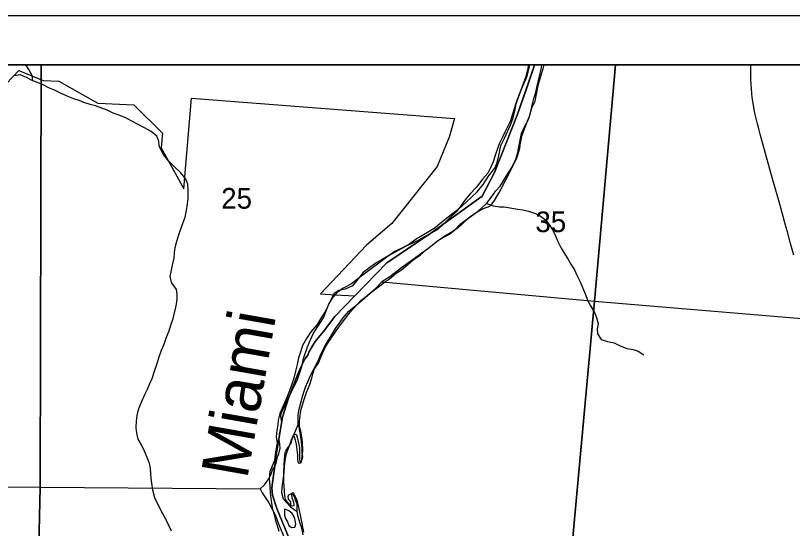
# Model space of a CAD drawing. Extents: x -38.1 to 35.9, y -2.7 to 28.5.
# Drawn here: x 10.189 to 11.759, y 18.793 to 19.831 of the extents above; entities that cross this region are included whole.
import ezdxf

# ---------------------------------------------------------------- set-up
doc = ezdxf.new("R2010")
doc.units = 0
for name, color, linetype in [('GM_X_Interchange_Ramps', 7, 'Continuous'), ('GM_X_Minor_River', 7, 'Continuous'), ('GM_X_Section', 7, 'Continuous'), ('GM_X_Township_Road', 7, 'Continuous'), ('GM_X_Township_Road_Text', 7, 'Continuous'), ('GM_X_US_Route', 7, 'Continuous'), ('SH_Border', 7, 'Continuous'), ('SH_Data', 7, 'Continuous')]:
    doc.layers.add(name, color=color, linetype=linetype)

msp = doc.modelspace()

# ---------------------------------------------------------------- linework, layer by layer
at = {"layer": 'GM_X_Interchange_Ramps'}
msp.add_lwpolyline([(11.7616, 19.346), (11.7552, 19.3694), (11.7486, 19.3933), (11.745, 19.4065), (11.7332, 19.449), (11.7292, 19.4634), (11.7188, 19.5005), (11.7044, 19.5513), (11.6938, 19.5909), (11.6918, 19.5987), (11.6885, 19.6113), (11.6838, 19.6306), (11.6825, 19.6367), (11.6793, 19.6537), (11.6777, 19.6647), (11.6769, 19.6727), (11.6767, 19.6746), (11.676, 19.682), (11.6753, 19.6926), (11.675, 19.6998), (11.6748, 19.7039), (11.6749, 19.7135), (11.6751, 19.7308)], dxfattribs=at)
at = {"layer": 'GM_X_Section'}
for points in [[(10.2234, 19.6988), (10.222, 19.7091), (10.2157, 19.7213), (10.209, 19.7308)], [(10.4494, 19.6035), (10.4366, 19.6105), (10.4234, 19.6167), (10.4114, 19.6237), (10.397, 19.6292), (10.3861, 19.6335), (10.374, 19.6393), (10.3631, 19.6436), (10.3502, 19.648), (10.3393, 19.6508), (10.3268, 19.6547), (10.317, 19.6586), (10.3064, 19.6625), (10.2928, 19.6676), (10.2792, 19.6735), (10.2683, 19.6793), (10.257, 19.684), (10.2446, 19.6906), (10.2332, 19.6949), (10.2234, 19.6988), (10.2106, 19.7051), (10.1978, 19.7109), (10.1856, 19.7084)], [(10.5039, 18.7871), (10.4976, 18.8001), (10.4932, 18.8104), (10.4862, 18.8226), (10.4765, 18.8406), (10.4699, 18.8548), (10.4659, 18.8704), (10.4635, 18.889), (10.4621, 18.902), (10.4611, 18.9145), (10.459, 18.9241), (10.4549, 18.9366), (10.449, 18.9489), (10.4431, 18.9619), (10.4364, 18.9734), (10.4336, 18.9859), (10.4322, 18.9962), (10.4327, 19.0103), (10.4344, 19.0213), (10.4376, 19.0353), (10.443, 19.0481), (10.4501, 19.0636), (10.4555, 19.075), (10.4602, 19.0863), (10.4649, 19.0965), (10.4704, 19.1132), (10.4739, 19.1249), (10.4779, 19.1382), (10.4838, 19.1537), (10.4888, 19.1654), (10.4936, 19.1798), (10.499, 19.193), (10.5022, 19.2044), (10.5069, 19.2176), (10.5113, 19.2343), (10.5137, 19.2468), (10.515, 19.257), (10.5151, 19.2665), (10.5141, 19.2764), (10.504, 19.2902), (10.5011, 19.3024), (10.5036, 19.3157), (10.5056, 19.3255), (10.5092, 19.3395), (10.5097, 19.3505), (10.5113, 19.3615), (10.5141, 19.3714), (10.5173, 19.3831), (10.5216, 19.3952), (10.5275, 19.4119), (10.5311, 19.4225), (10.5343, 19.4361), (10.5363, 19.4494), (10.5372, 19.4604), (10.5374, 19.4767), (10.5368, 19.4893), (10.5324, 19.4996), (10.5227, 19.5126), (10.5103, 19.5241), (10.4979, 19.5368), (10.4871, 19.5502), (10.479, 19.5671), (10.4779, 19.5766), (10.4743, 19.5865), (10.463, 19.5961), (10.4494, 19.6035)], [(11.1408, 19.4506), (11.1537, 19.4455), (11.1665, 19.4434), (11.1764, 19.4433), (11.2037, 19.4392), (11.2139, 19.4376), (11.2256, 19.4348), (11.2396, 19.43), (11.2497, 19.4246), (11.2606, 19.4165), (11.2685, 19.4058), (11.2752, 19.3954), (11.28, 19.3851), (11.2848, 19.3733), (11.2914, 19.3599), (11.2985, 19.3476), (11.3048, 19.3381), (11.3108, 19.3277), (11.3186, 19.3159), (11.3234, 19.3056), (11.3293, 19.293), (11.3403, 19.2662), (11.3448, 19.2551), (11.3507, 19.2433), (11.3585, 19.2299), (11.3629, 19.22), (11.3665, 19.207), (11.3645, 19.1968), (11.3648, 19.1869), (11.3726, 19.175), (11.3854, 19.1714), (11.3983, 19.1683), (11.4092, 19.1628), (11.4243, 19.1569), (11.4368, 19.1549), (11.447, 19.1517), (11.4583, 19.1444)]]:
    msp.add_lwpolyline(points, dxfattribs=at)
at = {"layer": 'GM_X_Township_Road'}
for p, q in [((10.7595, 19.0037), (10.7503, 18.9814)), ((10.7441, 18.8366), (10.7577, 18.827))]:
    msp.add_line(p, q, dxfattribs=at)
for points in [[(11.2256, 19.7308), (11.2234, 19.72), (11.2198, 19.7076), (11.2147, 19.6928), (11.2108, 19.6818), (11.2065, 19.6709), (11.2021, 19.6591), (11.1986, 19.6489), (11.1955, 19.6391), (11.1923, 19.6289), (11.1888, 19.6179), (11.1833, 19.6066), (11.1775, 19.5945), (11.1728, 19.5847), (11.1666, 19.5722), (11.1615, 19.5578), (11.1583, 19.5472), (11.154, 19.5344), (11.1489, 19.5223), (11.1435, 19.5117), (11.1331, 19.5001), (11.1196, 19.4827), (11.1073, 19.4696), (11.0969, 19.4568), (11.0873, 19.4436), (11.0792, 19.4338), (11.0673, 19.4218), (11.0535, 19.4083), (11.0427, 19.3986), (11.0298, 19.3911), (11.0168, 19.3833), (11.0049, 19.377), (10.9939, 19.3714), (10.9805, 19.3655), (10.9694, 19.3595), (10.9546, 19.3513), (10.9427, 19.3446), (10.9294, 19.3372), (10.9187, 19.3309), (10.9045, 19.3212), (10.8911, 19.3107), (10.8784, 19.2949), (10.8699, 19.2836), (10.8547, 19.2769), (10.8421, 19.2744), (10.8326, 19.2684), (10.8271, 19.2579), (10.8217, 19.2469), (10.8139, 19.2303), (10.805, 19.2171), (10.7984, 19.2054), (10.7853, 19.1904), (10.7765, 19.1772), (10.7687, 19.1632), (10.7651, 19.1515), (10.7608, 19.1382), (10.7576, 19.1249), (10.7544, 19.1109), (10.7508, 19.0969), (10.7465, 19.0825), (10.7422, 19.0715), (10.7367, 19.0579), (10.732, 19.047), (10.7277, 19.036), (10.7226, 19.0254), (10.7194, 19.0121), (10.7189, 19.0027), (10.7165, 18.9917), (10.7152, 18.9784), (10.7173, 18.9654), (10.7145, 18.9514), (10.7136, 18.9415), (10.712, 18.9305), (10.7065, 18.9177), (10.7026, 18.9078), (10.7009, 18.8946), (10.7022, 18.8778), (10.7032, 18.8649), (10.7053, 18.8489), (10.7074, 18.8348), (10.7103, 18.823), (10.7139, 18.8089), (10.7176, 18.7986), (10.7205, 18.7875)], [(10.7595, 19.0037), (10.7598, 19.0231), (10.7622, 19.0367), (10.765, 19.0473), (10.7678, 19.0572), (10.771, 19.0685), (10.7749, 19.0788), (10.7792, 19.0893), (10.785, 19.1022), (10.7908, 19.1135), (10.7955, 19.1234), (10.8014, 19.1354), (10.8056, 19.1456), (10.8126, 19.1589), (10.8189, 19.1706), (10.8277, 19.1845), (10.8355, 19.1977), (10.8424, 19.2075), (10.8505, 19.2192), (10.8625, 19.2324), (10.8763, 19.244), (10.8897, 19.2552), (10.9004, 19.265), (10.9123, 19.274), (10.9249, 19.2837), (10.9345, 19.2912), (10.9444, 19.2979), (10.9582, 19.3091), (10.9689, 19.3162), (10.982, 19.3278), (10.9919, 19.3357), (11.0072, 19.3465), (11.0187, 19.3567), (11.0283, 19.3641), (11.0417, 19.375), (11.0554, 19.3828), (11.0657, 19.3884), (11.0757, 19.3966), (11.088, 19.409), (11.1002, 19.418), (11.1098, 19.4247), (11.1213, 19.4337), (11.1309, 19.4416), (11.1408, 19.4506), (11.1497, 19.4622), (11.1593, 19.4758), (11.1682, 19.4856), (11.1751, 19.4965), (11.181, 19.5063), (11.1887, 19.5195), (11.1949, 19.5297), (11.1996, 19.5399), (11.2035, 19.5535), (11.2059, 19.5649), (11.2084, 19.5782), (11.2112, 19.5918), (11.2182, 19.6069), (11.2248, 19.619), (11.2295, 19.633), (11.2331, 19.6493), (11.2363, 19.6629), (11.2399, 19.675), (11.2427, 19.6887), (11.2459, 19.6993), (11.2491, 19.714), (11.2515, 19.725), (11.2526, 19.7308)], [(10.7503, 18.9814), (10.7524, 18.976), (10.7538, 18.9718), (10.7556, 18.9631), (10.7574, 18.952), (10.7584, 18.9418), (10.7587, 18.9323), (10.7597, 18.9258), (10.7631, 18.9246), (10.7658, 18.9261), (10.7678, 18.9329), (10.769, 18.9375), (10.7679, 18.9466), (10.7676, 18.9542), (10.767, 18.9626), (10.7656, 18.9725), (10.7646, 18.9823), (10.7635, 18.9903), (10.7621, 18.998), (10.7595, 19.0037)], [(10.7441, 18.8366), (10.73, 18.852), (10.7267, 18.8646), (10.7272, 18.876), (10.7289, 18.8855), (10.7314, 18.9052), (10.7323, 18.9193), (10.7344, 18.9344), (10.736, 18.9443), (10.7419, 18.9587), (10.7466, 18.9719), (10.7503, 18.9814)], [(10.7577, 18.827), (10.7575, 18.8418), (10.7546, 18.8498), (10.7528, 18.8559), (10.7502, 18.8605), (10.746, 18.8629), (10.7411, 18.861), (10.7392, 18.8584), (10.7398, 18.8523), (10.744, 18.8469), (10.7441, 18.8366)], [(10.735, 18.8314), (10.7324, 18.8319), (10.7323, 18.8243), (10.7322, 18.8193), (10.7341, 18.8132), (10.7381, 18.8059)], [(10.7381, 18.8059), (10.7411, 18.7991), (10.7463, 18.7948), (10.7532, 18.7955), (10.7551, 18.8012), (10.7537, 18.8088), (10.7523, 18.8149), (10.7478, 18.8233), (10.7411, 18.8283), (10.735, 18.8314)], [(10.7697, 18.7797), (10.7672, 18.7931), (10.7639, 18.803), (10.7595, 18.8163), (10.7577, 18.827)]]:
    msp.add_lwpolyline(points, dxfattribs=at)
at = {"layer": 'GM_X_US_Route'}
for points in [[(14.9146, 19.7308), (8.1146, 19.7308), (8.1146, 17.8763), (8.2228, 17.8761), (8.7564, 17.8708), (8.7662, 17.8706), (9.0262, 17.8689), (9.5019, 17.8671), (9.8985, 17.8644), (9.9118, 17.8643), (10.4152, 17.8803), (10.3361, 17.7853), (10.2437, 17.6904)], [(10.1436, 19.6658), (10.1955, 19.7198), (10.2441, 19.6996), (10.2763, 19.6978), (10.355, 19.6536), (10.4278, 19.6502), (10.4853, 19.593), (10.4826, 19.5629), (10.5287, 19.4803), (10.5441, 19.6633), (11.0757, 19.6226), (11.065, 19.5846), (11.041, 19.525), (10.9494, 19.4101), (10.8979, 19.3661), (10.8048, 19.2678), (10.8353, 19.2657), (10.8742, 19.2633), (10.9391, 19.3301), (11.028, 19.3906), (11.1314, 19.465), (11.1567, 19.5128), (11.2026, 19.6289), (11.237, 19.7281), (11.2375, 19.7308), (8.1146, 19.7308)], [(10.743, 18.7692), (10.717, 18.8331), (10.7082, 18.8602), (10.7069, 18.875), (10.7159, 18.9453), (10.7283, 19.0178), (10.7403, 19.0564), (10.76, 19.1071), (10.7663, 19.1222), (10.7737, 19.1366), (10.7791, 19.1437), (10.7819, 19.1509), (10.7939, 19.1713), (10.8109, 19.1916), (10.8341, 19.222), (10.8742, 19.2633), (10.9391, 19.3301), (11.028, 19.3906), (11.1314, 19.465), (11.1567, 19.5128), (11.2026, 19.6289), (11.2204, 19.6804), (11.237, 19.7281), (11.2375, 19.7308), (8.1146, 19.7308)], [(14.9146, 19.7308), (11.2375, 19.7308), (11.237, 19.7281), (11.2204, 19.6804), (11.2026, 19.6289), (11.1567, 19.5128), (11.1314, 19.465), (11.028, 19.3906), (10.9391, 19.3301), (10.8742, 19.2633), (10.8341, 19.222), (10.8109, 19.1916), (10.7939, 19.1713), (10.7819, 19.1509), (10.7791, 19.1437), (10.7737, 19.1366), (10.7663, 19.1222), (10.76, 19.1071), (10.7403, 19.0564), (10.7283, 19.0178), (10.7159, 18.9453), (10.7069, 18.875), (10.7082, 18.8602), (10.717, 18.8331), (10.743, 18.7692)], [(10.7715, 18.785), (10.7659, 18.8132), (10.7614, 18.8356), (10.7568, 18.8516), (10.751, 18.8634), (10.7487, 18.865), (10.7468, 18.8639), (10.746, 18.8605), (10.747, 18.8552), (10.7503, 18.846), (10.7509, 18.8415), (10.7509, 18.8396), (10.7478, 18.8381), (10.7448, 18.8389), (10.7389, 18.8451), (10.7344, 18.8512), (10.7327, 18.8592), (10.7306, 18.8873), (10.7309, 18.9055), (10.7316, 18.9232), (10.7331, 18.9399), (10.7336, 18.9463), (10.7348, 18.9489), (10.7391, 18.9561), (10.7429, 18.9613), (10.7461, 18.9677), (10.7485, 18.9756), (10.7501, 18.9805), (10.7517, 18.9835), (10.754, 18.9838), (10.7566, 18.9826), (10.7576, 18.9777), (10.7601, 18.9685), (10.7622, 18.9568), (10.7626, 18.9408), (10.7625, 18.9321), (10.7632, 18.9283), (10.7643, 18.9264), (10.7658, 18.926), (10.7666, 18.9279), (10.7674, 18.9336), (10.7689, 18.9498), (10.7688, 18.968), (10.7661, 18.9862), (10.7626, 18.9988), (10.7624, 19.0094), (10.7637, 19.0204), (10.7655, 19.0317), (10.7703, 19.0494), (10.7768, 19.0678), (10.7835, 19.0844), (10.788, 19.0998), (10.79, 19.1077), (10.7924, 19.1145), (10.7963, 19.1212), (10.801, 19.1276), (10.8057, 19.1392), (10.8113, 19.1516), (10.816, 19.1614), (10.8222, 19.1715), (10.8367, 19.1924), (10.8491, 19.2104), (10.8654, 19.2309), (10.8774, 19.2447), (10.8867, 19.254), (10.8944, 19.2603), (10.9159, 19.2784), (10.9287, 19.2918), (11.3585, 19.2527), (11.2671, 18.2524)], [(10.2156, 17.8613), (10.2384, 18.8764), (10.683, 18.873), (10.687, 18.8646), (10.7002, 18.8447), (10.7141, 18.819), (10.7203, 18.8019), (10.7308, 18.7767)]]:
    msp.add_lwpolyline(points, dxfattribs=at)
for points in [[(10.2402, 19.7308), (9.2344, 19.7308), (9.2246, 18.878), (10.2384, 18.8764)], [(11.2284, 19.7308), (10.2402, 19.7308), (10.2384, 18.8764), (10.683, 18.873), (10.6915, 18.8812), (10.7004, 18.8931), (10.7051, 18.9033), (10.7079, 18.9112), (10.713, 18.9198), (10.715, 18.9251), (10.7179, 18.9379), (10.7207, 18.9439), (10.7223, 18.9495), (10.7231, 18.9556), (10.7229, 18.9636), (10.7216, 18.973), (10.7218, 18.9833), (10.7238, 18.9927), (10.7259, 19.0036), (10.7268, 19.0085), (10.7254, 19.015), (10.7247, 19.0203), (10.7256, 19.0256), (10.7291, 19.032), (10.7422, 19.062), (10.7575, 19.0924), (10.7619, 19.1041), (10.7671, 19.1207), (10.7709, 19.1369), (10.7789, 19.1606), (10.784, 19.1734), (10.7911, 19.188), (10.8036, 19.2075), (10.811, 19.2191), (10.8142, 19.2281), (10.8221, 19.2465), (10.8304, 19.2607), (10.8404, 19.2723), (10.8489, 19.2786), (10.8584, 19.2833), (10.8676, 19.2884), (10.8834, 19.3003), (10.9387, 19.3424), (10.954, 19.3531), (10.9686, 19.36), (10.9827, 19.3677), (10.9981, 19.3788), (11.018, 19.3901), (11.0364, 19.4019), (11.0418, 19.4067), (11.0695, 19.429), (11.0752, 19.433), (11.0848, 19.4393), (11.0987, 19.4523), (11.1218, 19.4738), (11.1335, 19.4891), (11.1444, 19.5056), (11.1572, 19.522), (11.1615, 19.531), (11.164, 19.5412), (11.1665, 19.5536), (11.1678, 19.5623), (11.1702, 19.5691), (11.1772, 19.5826), (11.1895, 19.6108), (11.1947, 19.6239), (11.1976, 19.6375), (11.2005, 19.6518), (11.2049, 19.6658), (11.2113, 19.6819), (11.2228, 19.7079), (11.2273, 19.7267)], [(11.4013, 19.7308), (11.2562, 19.7308), (11.2545, 19.7228), (11.2444, 19.6893), (11.2381, 19.6572), (11.2369, 19.6538), (11.2346, 19.6504), (11.2326, 19.6471), (11.2265, 19.6264), (11.2166, 19.6008), (11.2114, 19.5861), (11.208, 19.5691), (11.2072, 19.562), (11.2019, 19.5435), (11.1854, 19.5105), (11.1696, 19.4793), (11.1626, 19.4681), (11.1559, 19.4565), (11.149, 19.4472), (11.1466, 19.4446), (11.134, 19.4399), (11.118, 19.4307), (11.1041, 19.4204), (11.0829, 19.4011), (11.0676, 19.3907), (11.0561, 19.3845), (11.0461, 19.3775), (11.0219, 19.3586), (10.9904, 19.3358), (10.9689, 19.3199), (10.9451, 19.3021), (10.9287, 19.2918), (11.3585, 19.2527)], [(12.4074, 19.7308), (11.4013, 19.7308), (11.3585, 19.2527), (12.358, 19.1694)], [(11.3585, 19.2527), (12.358, 19.1694), (12.2713, 18.1647), (11.2671, 18.2524)], [(9.2246, 18.878), (10.2384, 18.8764), (10.2156, 17.8613), (9.2136, 17.8669)]]:
    msp.add_lwpolyline(points, close=True, dxfattribs=at)
at = {"layer": 'SH_Border'}
msp.add_line((8.1146, 19.7308), (14.9146, 19.7308), dxfattribs=at)
at = {"layer": 'SH_Data'}
msp.add_line((8.0146, 19.8308), (15.0146, 19.8308), dxfattribs=at)

# ---------------------------------------------------------------- texts
at = {"layer": 'GM_X_Minor_River'}
for s, p in [('25', (10.6043, 19.4399)), ('35', (11.2393, 19.3924))]:
    msp.add_text(s, height=0.04186, rotation=0, dxfattribs=at).set_placement(p)
at = {"layer": 'GM_X_Township_Road_Text'}
msp.add_text('Miami', height=0.0948, rotation=79.9884, dxfattribs=at).set_placement((10.6566, 18.8908))

doc.saveas('drawing.dxf')
